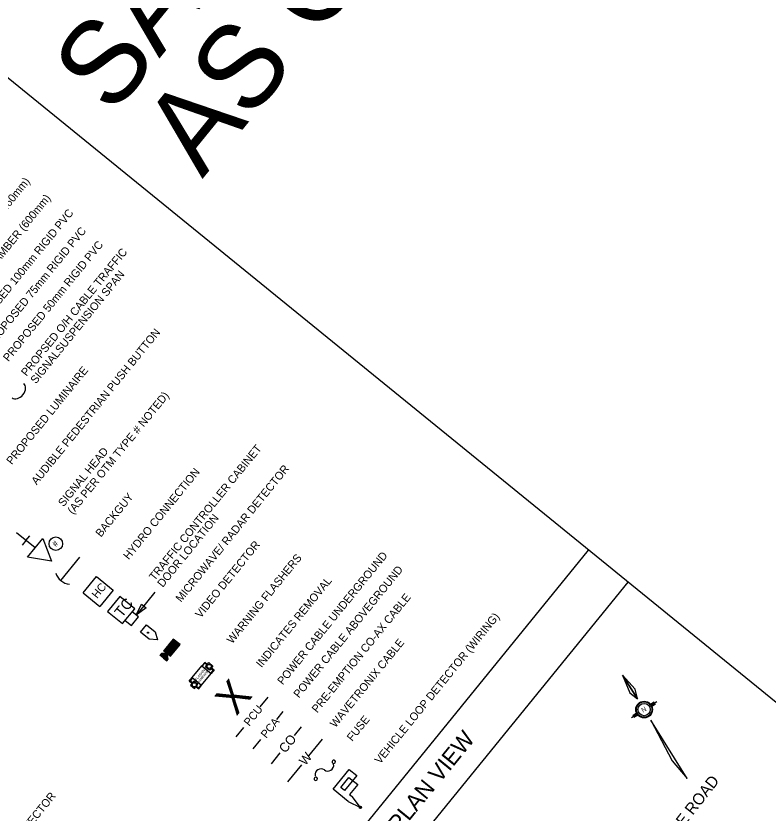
# Model space of a CAD drawing. Extents: x 592613 to 600223, y 4837996 to 4840103.
# Drawn here: x 592933.72 to 592974.48, y 4839262.21 to 4839305.4 of the extents above; entities that cross this region are included whole.
import ezdxf

# ---------------------------------------------------------------- set-up
doc = ezdxf.new("R2010")
doc.units = 0
for name, color, linetype in [('ENG_BORDER', 7, 'Continuous'), ('ENG_TITLEBLOCK', 7, 'Continuous'), ('ENG_TX_TITLEBLOCK', 7, 'Continuous'), ('Level 32', 7, 'Continuous'), ('Level 33', 7, 'Continuous'), ('TCS_BACKGUY', 7, 'Continuous'), ('TCS_CONTROLLER', 7, 'Continuous'), ('TCS_FUSE', 7, 'Continuous'), ('TCS_HYDROSUPPLY', 7, 'Continuous'), ('TCS_LEGEND', 7, 'Continuous'), ('TCS_LOOP', 7, 'Continuous'), ('TCS_RADAR', 7, 'Continuous'), ('TCS_REMOVAL', 7, 'Continuous'), ('TCS_SIGN', 7, 'Continuous'), ('TCS_SIGNALHEAD', 7, 'Continuous'), ('TCS_SPAN-NEW', 7, 'Continuous'), ('TCS_VIDEO', 7, 'Continuous'), ('TCS_WR_CO', 7, 'Continuous'), ('TCS_WR_PCA', 7, 'Continuous'), ('TCS_WR_PCU', 7, 'Continuous'), ('TCS_WR_W', 7, 'Continuous')]:
    doc.layers.add(name, color=color, linetype=linetype)

msp = doc.modelspace()

# ---------------------------------------------------------------- linework, layer by layer
at = {"layer": 'ENG_BORDER'}
msp.add_line((593034.225, 4839220.017), (592929.842, 4839304.827), dxfattribs=at)
at = {"layer": 'ENG_TITLEBLOCK'}
msp.add_line((592939.353, 4839240.83), (592966.893, 4839274.724), dxfattribs=at)
msp.add_line((592939.353, 4839240.83), (592966.893, 4839274.724), dxfattribs=at)
msp.add_lwpolyline([(592937.219, 4839242.565), (592964.758, 4839276.458)], dxfattribs=at)
msp.add_lwpolyline([(592937.219, 4839242.565), (592964.758, 4839276.458)], dxfattribs=at)
at = {"layer": 'ENG_TX_TITLEBLOCK'}
for p, q in [((592968.114, 4839268.107), (592968.318, 4839268.235)), ((592968.149, 4839268.058), (592968.454, 4839268.25)), ((592968.177, 4839268.006), (592968.382, 4839268.134)), ((592967.081, 4839267.39), (592967.386, 4839267.581)), ((592967.153, 4839267.506), (592967.358, 4839267.634)), ((592967.217, 4839267.404), (592967.421, 4839267.532))]:
    msp.add_line(p, q, dxfattribs=at)
for points in [[(592966.6, 4839269.684), (592966.985, 4839268.73), (592967.407, 4839268.396)], [(592966.6, 4839269.684), (592967.407, 4839268.396), (592967.29, 4839268.921)], [(592968.128, 4839267.243), (592969.292, 4839265.046), (592970.103, 4839264.091)]]:
    msp.add_lwpolyline(points, close=True, dxfattribs=at)
for radius in [0.45, 0.418, 0.336]:
    msp.add_circle((592967.767, 4839267.82), radius, dxfattribs=at)
at = {"layer": 'Level 32'}
for p, q in [((592968.114, 4839268.107), (592968.318, 4839268.235)), ((592968.149, 4839268.058), (592968.454, 4839268.25)), ((592968.177, 4839268.006), (592968.382, 4839268.134)), ((592967.081, 4839267.39), (592967.386, 4839267.581)), ((592967.153, 4839267.506), (592967.358, 4839267.634)), ((592967.217, 4839267.404), (592967.421, 4839267.532))]:
    msp.add_line(p, q, dxfattribs=at)
for points in [[(592966.6, 4839269.684), (592966.985, 4839268.73), (592967.407, 4839268.396)], [(592966.6, 4839269.684), (592967.407, 4839268.396), (592967.29, 4839268.921)], [(592968.128, 4839267.243), (592969.292, 4839265.046), (592970.103, 4839264.091)]]:
    msp.add_lwpolyline(points, close=True, dxfattribs=at)
for radius in [0.45, 0.418, 0.336]:
    msp.add_circle((592967.767, 4839267.82), radius, dxfattribs=at)
at = {"layer": 'TCS_BACKGUY'}
msp.add_line((592936.146, 4839274.811), (592937.182, 4839276.085), dxfattribs=at)
msp.add_arc((592936.692, 4839275.462), 0.849, 196.7975, 265.0147, dxfattribs=at)
at = {"layer": 'TCS_CONTROLLER'}
for p, q in [((592939.348, 4839273.938), (592938.692, 4839273.13)), ((592940.156, 4839273.282), (592939.348, 4839273.938)), ((592941.252, 4839274.177), (592940.347, 4839273.063)), ((592938.692, 4839273.13), (592939.499, 4839272.474)), ((592939.499, 4839272.474), (592940.156, 4839273.282)), ((592940.364, 4839272.843), (592940.028, 4839273.117)), ((592939.645, 4839272.645), (592939.981, 4839272.372)), ((592939.981, 4839272.372), (592940.364, 4839272.843))]:
    msp.add_line(p, q, dxfattribs=at)
msp.add_lwpolyline([(592940.246, 4839272.939), (592940.525, 4839273.535), (592940.772, 4839273.334), (592940.772, 4839273.334)], close=True, dxfattribs=at)
at = {"layer": 'TCS_FUSE'}
for centre, radius, start, end in [((592950.625, 4839264.804), 0.319, 233.6234, 10.2722), ((592950.948, 4839264.989), 0.0867, 50.9061, 230.9061), ((592950.948, 4839264.989), 0.0867, 230.9061, 50.9061), ((592950.247, 4839264.29), 0.319, 53.6234, 190.2722), ((592949.971, 4839264.068), 0.0867, 50.9061, 230.9061), ((592949.971, 4839264.068), 0.0867, 230.9061, 50.9061)]:
    msp.add_arc(centre, radius, start, end, dxfattribs=at)
at = {"layer": 'TCS_HYDROSUPPLY'}
for p, q in [((592937.364, 4839274.135), (592938.092, 4839275.032)), ((592938.092, 4839275.032), (592938.999, 4839274.295)), ((592938.999, 4839274.295), (592938.27, 4839273.399)), ((592937.364, 4839274.135), (592938.271, 4839273.398))]:
    msp.add_line(p, q, dxfattribs=at)
at = {"layer": 'TCS_LOOP'}
for p, q in [((592950.913, 4839263.499), (592951.788, 4839264.576)), ((592952.192, 4839264.248), (592951.536, 4839263.44)), ((592951.788, 4839264.576), (592952.192, 4839264.248)), ((592951.334, 4839263.604), (592951.771, 4839264.143)), ((592951.771, 4839264.143), (592952.243, 4839263.76)), ((592951.721, 4839262.843), (592950.913, 4839263.499)), ((592951.536, 4839263.44), (592951.334, 4839263.604)), ((592952.243, 4839263.76), (592951.805, 4839263.222)), ((592951.805, 4839263.222), (592951.945, 4839263.108)), ((592952.393, 4839262.521), (592951.945, 4839263.108)), ((592951.721, 4839262.843), (592952.393, 4839262.521)), ((592952.335, 4839262.504), (592952.333, 4839262.525)), ((592952.34, 4839262.492), (592952.336, 4839262.538)), ((592952.345, 4839262.485), (592952.338, 4839262.545)), ((592952.349, 4839262.48), (592952.341, 4839262.551)), ((592952.353, 4839262.476), (592952.345, 4839262.556)), ((592952.357, 4839262.473), (592952.348, 4839262.56)), ((592952.361, 4839262.47), (592952.351, 4839262.563)), ((592952.365, 4839262.468), (592952.354, 4839262.566)), ((592952.368, 4839262.466), (592952.358, 4839262.569)), ((592952.372, 4839262.464), (592952.361, 4839262.571)), ((592952.376, 4839262.463), (592952.365, 4839262.573)), ((592952.38, 4839262.462), (592952.368, 4839262.575)), ((592952.383, 4839262.462), (592952.372, 4839262.576)), ((592952.387, 4839262.461), (592952.375, 4839262.578)), ((592952.391, 4839262.461), (592952.379, 4839262.578)), ((592952.394, 4839262.461), (592952.382, 4839262.579)), ((592952.398, 4839262.461), (592952.386, 4839262.58)), ((592952.402, 4839262.461), (592952.389, 4839262.58)), ((592952.405, 4839262.462), (592952.393, 4839262.58)), ((592952.409, 4839262.463), (592952.397, 4839262.58)), ((592952.412, 4839262.464), (592952.4, 4839262.58)), ((592952.416, 4839262.465), (592952.404, 4839262.579)), ((592952.419, 4839262.467), (592952.408, 4839262.578)), ((592952.423, 4839262.469), (592952.411, 4839262.577)), ((592952.426, 4839262.471), (592952.415, 4839262.576)), ((592952.429, 4839262.473), (592952.419, 4839262.574)), ((592952.433, 4839262.476), (592952.423, 4839262.572)), ((592952.436, 4839262.479), (592952.427, 4839262.57)), ((592952.439, 4839262.483), (592952.431, 4839262.567)), ((592952.442, 4839262.488), (592952.435, 4839262.563)), ((592952.446, 4839262.493), (592952.439, 4839262.559)), ((592952.449, 4839262.499), (592952.443, 4839262.553)), ((592952.451, 4839262.509), (592952.447, 4839262.544))]:
    msp.add_line(p, q, dxfattribs=at)
msp.add_circle((592952.393, 4839262.521), 0.0597, dxfattribs=at)
at = {"layer": 'TCS_RADAR'}
msp.add_lwpolyline([(592940.479, 4839272.017), (592940.803, 4839272.416), (592941.272, 4839272.035), (592941.385, 4839271.604), (592940.948, 4839271.637)], close=True, dxfattribs=at)
for centre, radius in [((592940.878, 4839271.987), 0.0279), ((592940.88, 4839271.989), 0.0254), ((592940.883, 4839271.988), 0.0231), ((592940.885, 4839271.99), 0.021), ((592940.885, 4839271.99), 0.021), ((592940.886, 4839271.992), 0.0191)]:
    msp.add_circle(centre, radius, dxfattribs=at)
at = {"layer": 'TCS_SIGN'}
for p, q in [((592943.95, 4839270.378), (592943.793, 4839270.185)), ((592943.955, 4839270.327), (592943.821, 4839270.162)), ((592944.092, 4839270.263), (592943.95, 4839270.378)), ((592944.069, 4839270.234), (592943.955, 4839270.327)), ((592943.275, 4839269.548), (592943.793, 4839270.185)), ((592943.793, 4839270.185), (592944.302, 4839269.771)), ((592944.408, 4839269.959), (592944.274, 4839269.794)), ((592944.294, 4839270.052), (592944.408, 4839269.959)), ((592944.459, 4839269.965), (592944.302, 4839269.771)), ((592944.316, 4839270.08), (592944.459, 4839269.965)), ((592943.118, 4839269.355), (592943.275, 4839269.548)), ((592943.169, 4839269.36), (592943.303, 4839269.525)), ((592943.275, 4839269.548), (592943.784, 4839269.134)), ((592943.784, 4839269.134), (592944.302, 4839269.771)), ((592943.26, 4839269.239), (592943.118, 4839269.355)), ((592943.283, 4839269.267), (592943.169, 4839269.36)), ((592943.485, 4839269.057), (592943.627, 4839268.941)), ((592943.508, 4839269.085), (592943.622, 4839268.992)), ((592943.622, 4839268.992), (592943.756, 4839269.157)), ((592943.627, 4839268.941), (592943.784, 4839269.134))]:
    msp.add_line(p, q, dxfattribs=at)
for points in [[(592944.396, 4839270.178), (592944.214, 4839269.954), (592943.99, 4839270.136), (592944.172, 4839270.361)], [(592943.405, 4839268.959), (592943.587, 4839269.183), (592943.363, 4839269.365), (592943.181, 4839269.141)]]:
    msp.add_lwpolyline(points, close=True, dxfattribs=at)
for centre in [(592944.193, 4839270.157), (592943.384, 4839269.162)]:
    msp.add_circle(centre, 0.111, dxfattribs=at)
at = {"layer": 'TCS_SIGNALHEAD'}
for p, q in [((592934.766, 4839276.577), (592933.756, 4839277.398)), ((592934.261, 4839276.987), (592934.466, 4839277.24)), ((592934.261, 4839276.987), (592934.056, 4839276.735)), ((592934.356, 4839276.072), (592935.176, 4839277.082)), ((592935.176, 4839277.082), (592935.641, 4839275.867)), ((592935.641, 4839275.867), (592934.356, 4839276.072))]:
    msp.add_line(p, q, dxfattribs=at)
msp.add_circle((592935.884, 4839276.805), 0.368, dxfattribs=at)
at = {"layer": 'TCS_SPAN-NEW'}
msp.add_ellipse((592933.83, 4839285.101), major_axis=(0.315, 0.388), ratio=0.7, start_param=3.141593, end_param=6.283185, dxfattribs=at)
at = {"layer": 'TCS_VIDEO'}
for p, q in [((592942.286, 4839270.937), (592942.217, 4839271.598)), ((592942.299, 4839270.953), (592942.23, 4839271.614)), ((592942.311, 4839270.969), (592942.243, 4839271.63)), ((592942.324, 4839270.985), (592942.257, 4839271.633)), ((592942.337, 4839271.001), (592942.273, 4839271.62)), ((592942.35, 4839271.017), (592942.289, 4839271.607)), ((592942.363, 4839271.033), (592942.305, 4839271.594)), ((592941.9, 4839270.876), (592941.869, 4839271.17)), ((592941.915, 4839270.863), (592941.882, 4839271.185)), ((592941.931, 4839270.85), (592941.895, 4839271.201)), ((592941.947, 4839270.837), (592941.908, 4839271.217)), ((592941.963, 4839270.824), (592941.921, 4839271.233)), ((592941.979, 4839270.811), (592941.934, 4839271.249)), ((592941.995, 4839270.799), (592941.947, 4839271.265)), ((592942.011, 4839270.786), (592941.959, 4839271.281)), ((592942.026, 4839270.773), (592941.972, 4839271.296)), ((592942.042, 4839270.76), (592941.985, 4839271.312)), ((592942.058, 4839270.747), (592941.998, 4839271.328)), ((592942.074, 4839270.734), (592942.011, 4839271.344)), ((592942.09, 4839270.721), (592942.024, 4839271.36)), ((592942.105, 4839270.715), (592942.037, 4839271.376)), ((592942.118, 4839270.731), (592942.05, 4839271.392)), ((592942.131, 4839270.747), (592942.063, 4839271.408)), ((592942.144, 4839270.763), (592942.075, 4839271.423)), ((592942.157, 4839270.779), (592942.088, 4839271.439)), ((592942.17, 4839270.795), (592942.101, 4839271.455)), ((592942.182, 4839270.811), (592942.114, 4839271.471)), ((592942.195, 4839270.826), (592942.127, 4839271.487)), ((592942.208, 4839270.842), (592942.14, 4839271.503)), ((592942.221, 4839270.858), (592942.153, 4839271.519)), ((592942.234, 4839270.874), (592942.166, 4839271.535)), ((592942.247, 4839270.89), (592942.179, 4839271.55)), ((592942.26, 4839270.906), (592942.192, 4839271.566)), ((592942.273, 4839270.922), (592942.204, 4839271.582)), ((592942.376, 4839271.049), (592942.321, 4839271.582)), ((592942.389, 4839271.064), (592942.337, 4839271.569)), ((592942.402, 4839271.08), (592942.352, 4839271.556)), ((592942.415, 4839271.096), (592942.368, 4839271.543)), ((592942.427, 4839271.112), (592942.384, 4839271.53)), ((592942.44, 4839271.128), (592942.4, 4839271.517)), ((592942.453, 4839271.144), (592942.416, 4839271.504)), ((592942.466, 4839271.16), (592942.432, 4839271.491)), ((592942.479, 4839271.176), (592942.448, 4839271.478)), ((592942.492, 4839271.191), (592942.464, 4839271.465)), ((592942.505, 4839271.207), (592942.479, 4839271.453)), ((592942.518, 4839271.223), (592942.495, 4839271.44)), ((592942.531, 4839271.239), (592942.511, 4839271.427)), ((592942.543, 4839271.255), (592942.527, 4839271.414)), ((592942.556, 4839271.271), (592942.543, 4839271.401)), ((592942.569, 4839271.287), (592942.559, 4839271.388)), ((592942.582, 4839271.302), (592942.575, 4839271.375)), ((592942.595, 4839271.318), (592942.591, 4839271.362)), ((592942.608, 4839271.334), (592942.606, 4839271.349)), ((592941.611, 4839270.851), (592941.537, 4839270.76)), ((592941.537, 4839270.76), (592941.719, 4839270.612)), ((592941.542, 4839270.756), (592941.541, 4839270.765)), ((592941.558, 4839270.743), (592941.554, 4839270.781)), ((592941.573, 4839270.73), (592941.567, 4839270.797)), ((592941.589, 4839270.717), (592941.579, 4839270.813)), ((592941.605, 4839270.704), (592941.592, 4839270.829)), ((592941.621, 4839270.691), (592941.605, 4839270.845)), ((592941.92, 4839270.859), (592941.611, 4839270.851)), ((592941.637, 4839270.679), (592941.619, 4839270.851)), ((592941.653, 4839270.666), (592941.634, 4839270.852)), ((592941.669, 4839270.653), (592941.648, 4839270.852)), ((592941.685, 4839270.64), (592941.663, 4839270.853)), ((592941.7, 4839270.627), (592941.677, 4839270.853)), ((592941.716, 4839270.614), (592941.691, 4839270.853)), ((592941.732, 4839270.601), (592941.706, 4839270.854)), ((592941.748, 4839270.588), (592941.72, 4839270.854)), ((592941.764, 4839270.575), (592941.735, 4839270.855)), ((592941.741, 4839271.005), (592941.74, 4839271.011)), ((592941.78, 4839270.563), (592941.749, 4839270.855)), ((592941.757, 4839270.992), (592941.753, 4839271.027)), ((592941.796, 4839270.55), (592941.764, 4839270.855)), ((592941.773, 4839270.979), (592941.766, 4839271.043)), ((592941.811, 4839270.537), (592941.778, 4839270.856)), ((592941.788, 4839270.966), (592941.779, 4839271.058)), ((592941.804, 4839270.953), (592941.792, 4839271.074)), ((592941.827, 4839270.524), (592941.793, 4839270.856)), ((592941.82, 4839270.94), (592941.805, 4839271.09)), ((592941.843, 4839270.511), (592941.807, 4839270.856)), ((592941.836, 4839270.927), (592941.818, 4839271.106)), ((592941.859, 4839270.498), (592941.822, 4839270.857)), ((592941.852, 4839270.915), (592941.83, 4839271.122)), ((592941.875, 4839270.485), (592941.836, 4839270.857)), ((592941.868, 4839270.902), (592941.843, 4839271.138)), ((592941.891, 4839270.472), (592941.851, 4839270.858)), ((592941.884, 4839270.889), (592941.856, 4839271.154)), ((592941.906, 4839270.47), (592941.865, 4839270.858)), ((592941.918, 4839270.486), (592941.88, 4839270.858)), ((592941.931, 4839270.502), (592941.894, 4839270.859)), ((592941.944, 4839270.517), (592941.909, 4839270.859)), ((592941.975, 4839270.555), (592941.92, 4839270.859)), ((592941.957, 4839270.533), (592941.928, 4839270.812)), ((592941.719, 4839270.612), (592941.901, 4839270.464)), ((592941.901, 4839270.464), (592941.975, 4839270.555)), ((592941.97, 4839270.549), (592941.962, 4839270.626))]:
    msp.add_line(p, q, dxfattribs=at)
msp.add_lwpolyline([(592942.102, 4839270.711), (592942.615, 4839271.343), (592942.25, 4839271.639), (592941.738, 4839271.008), (592941.92, 4839270.859), (592942.102, 4839270.711)], dxfattribs=at)
at = {"layer": 'TCS_WR_CO'}
for p, q in [((592948.82, 4839266.417), (592949.205, 4839266.891)), ((592947.571, 4839264.879), (592948.047, 4839265.466))]:
    msp.add_line(p, q, dxfattribs=at)
at = {"layer": 'TCS_WR_PCA'}
for p, q in [((592947.854, 4839267.277), (592948.211, 4839267.717)), ((592946.972, 4839266.193), (592946.559, 4839265.683))]:
    msp.add_line(p, q, dxfattribs=at)
at = {"layer": 'TCS_WR_PCU'}
for p, q in [((592946.958, 4839267.962), (592947.383, 4839268.485)), ((592946.051, 4839266.846), (592945.637, 4839266.337))]:
    msp.add_line(p, q, dxfattribs=at)
at = {"layer": 'TCS_WR_W'}
for p, q in [((592949.603, 4839265.313), (592950.336, 4839266.216)), ((592948.463, 4839263.911), (592949.211, 4839264.83))]:
    msp.add_line(p, q, dxfattribs=at)

# ---------------------------------------------------------------- texts
at = {"layer": 'ENG_TX_TITLEBLOCK'}
for s, height, rotation, p in [('SAMPLE - TRAFFIC ', 4.52865, 50.906, (592938.939, 4839299.946)), ('AS CONSTRUCTED', 4.52865, 50.906, (592943.824, 4839296.556)), ('N', 0.25, 32.0574, (592967.713, 4839267.649)), ('DETECTION ZONE - PLAN VIEW', 0.9, 50.9062, (592947.124, 4839252.03))]:
    msp.add_text(s, height=height, rotation=rotation, dxfattribs=at).set_placement(p)
at = {"layer": 'Level 32'}
msp.add_text('N', height=0.25, rotation=32.0574, dxfattribs=at).set_placement((592967.713, 4839267.649))
at = {"layer": 'Level 33'}
msp.add_text('REMEMBRANCE ROAD', height=0.61958, rotation=52.007, dxfattribs=at).set_placement((592966.237, 4839256.731))
at = {"layer": 'TCS_CONTROLLER'}
msp.add_text('TC', height=0.5783, rotation=50.9061, dxfattribs=at).set_placement((592939.464, 4839272.763))
at = {"layer": 'TCS_HYDROSUPPLY'}
msp.add_text('HC', height=0.4337, rotation=50.9061, dxfattribs=at).set_placement((592938.122, 4839273.806))
at = {"layer": 'TCS_LEGEND'}
for s, height, p in [('PROPOSED ELECTRICAL CHAMBER (460mm)', 0.43374, (592926.584, 4839286.675)), ('PROPOSED ELECTRICAL CHAMBER (600mm)', 0.43374, (592927.709, 4839285.76)), ('PROPOSED 100mm RIGID PVC', 0.43374, (592931.504, 4839288.114)), ('PROPOSED 75mm RIGID PVC', 0.43374, (592932.395, 4839287.39)), ('PROPOSED 50mm RIGID PVC', 0.43374, (592933.317, 4839286.641)), ('PROPSED O/H CABLE TRAFFIC', 0.43374, (592934.297, 4839285.845)), ('SIGNALSUSPENSION SPAN', 0.43374, (592934.802, 4839285.434)), ('AUDIBLE PEDESTRIAN PUSH BUTTON', 0.43374, (592934.846, 4839279.962)), ('PROPOSED LUMINAIRE', 0.43374, (592933.498, 4839281.057)), ('(AS PER OTM TYPE # NOTED)', 0.43374, (592936.807, 4839278.368)), ('SIGNAL HEAD ', 0.43374, (592936.302, 4839278.778)), ('TRAFFIC CONTROLLER CABINET', 0.43374, (592941.234, 4839274.771)), ('HYDRO CONNECTION', 0.43374, (592939.836, 4839275.907)), ('MICROWAVE/ RADAR DETECTOR', 0.43374, (592942.669, 4839273.605)), ('BACKGUY', 0.4337, (592938.328, 4839277.132)), ('DOOR LOCATION', 0.43374, (592941.68, 4839274.409)), ('VIDEO DETECTOR', 0.43374, (592943.73, 4839272.743)), ('WARNING FLASHERS', 0.43374, (592945.443, 4839271.352)), ('POWER CABLE UNDERGROUND', 0.43374, (592948.182, 4839269.126)), ('POWER CABLE ABOVEGROUND', 0.43374, (592949.057, 4839268.415)), ('INDICATES REMOVAL', 0.43374, (592947.032, 4839270.061)), ('PRE-EMPTION CO-AX CABLE', 0.43374, (592950.048, 4839267.61)), ('VEHICLE LOOP DETECTOR (WIRING)', 0.43374, (592953.457, 4839264.84)), ('WAVETRONIX CABLE', 0.43374, (592951.038, 4839266.806)), ('FUSE', 0.4337, (592951.949, 4839266.065)), ('VEHICLE LOOP DETECTOR', 0.43374, (592931.117, 4839257.22))]:
    msp.add_text(s, height=height, rotation=50.9061, dxfattribs=at).set_placement(p)
at = {"layer": 'TCS_REMOVAL'}
msp.add_text('X', height=1.631, rotation=50.9061, dxfattribs=at).set_placement((592945.666, 4839267.431))
at = {"layer": 'TCS_SIGN'}
for s, p in [('FLASHING', (592943.516, 4839269.383)), ('WARNING', (592943.663, 4839269.264))]:
    msp.add_text(s, height=0.1265, rotation=50.9061, dxfattribs=at).set_placement(p)
at = {"layer": 'TCS_SIGNALHEAD'}
msp.add_text('#', height=0.325, rotation=50.9061, dxfattribs=at).set_placement((592935.896, 4839276.613))
at = {"layer": 'TCS_WR_CO'}
msp.add_text('CO', height=0.506, rotation=50.9061, dxfattribs=at).set_placement((592948.319, 4839265.426))
at = {"layer": 'TCS_WR_PCA'}
msp.add_text('PCA', height=0.4303, rotation=50.9061, dxfattribs=at).set_placement((592947.285, 4839266.236))
at = {"layer": 'TCS_WR_PCU'}
msp.add_text('PCU', height=0.4303, rotation=50.9061, dxfattribs=at).set_placement((592946.363, 4839266.89))
at = {"layer": 'TCS_WR_W'}
msp.add_text('W', height=0.495, rotation=50.9061, dxfattribs=at).set_placement((592949.41, 4839264.754))

doc.saveas('drawing.dxf')
